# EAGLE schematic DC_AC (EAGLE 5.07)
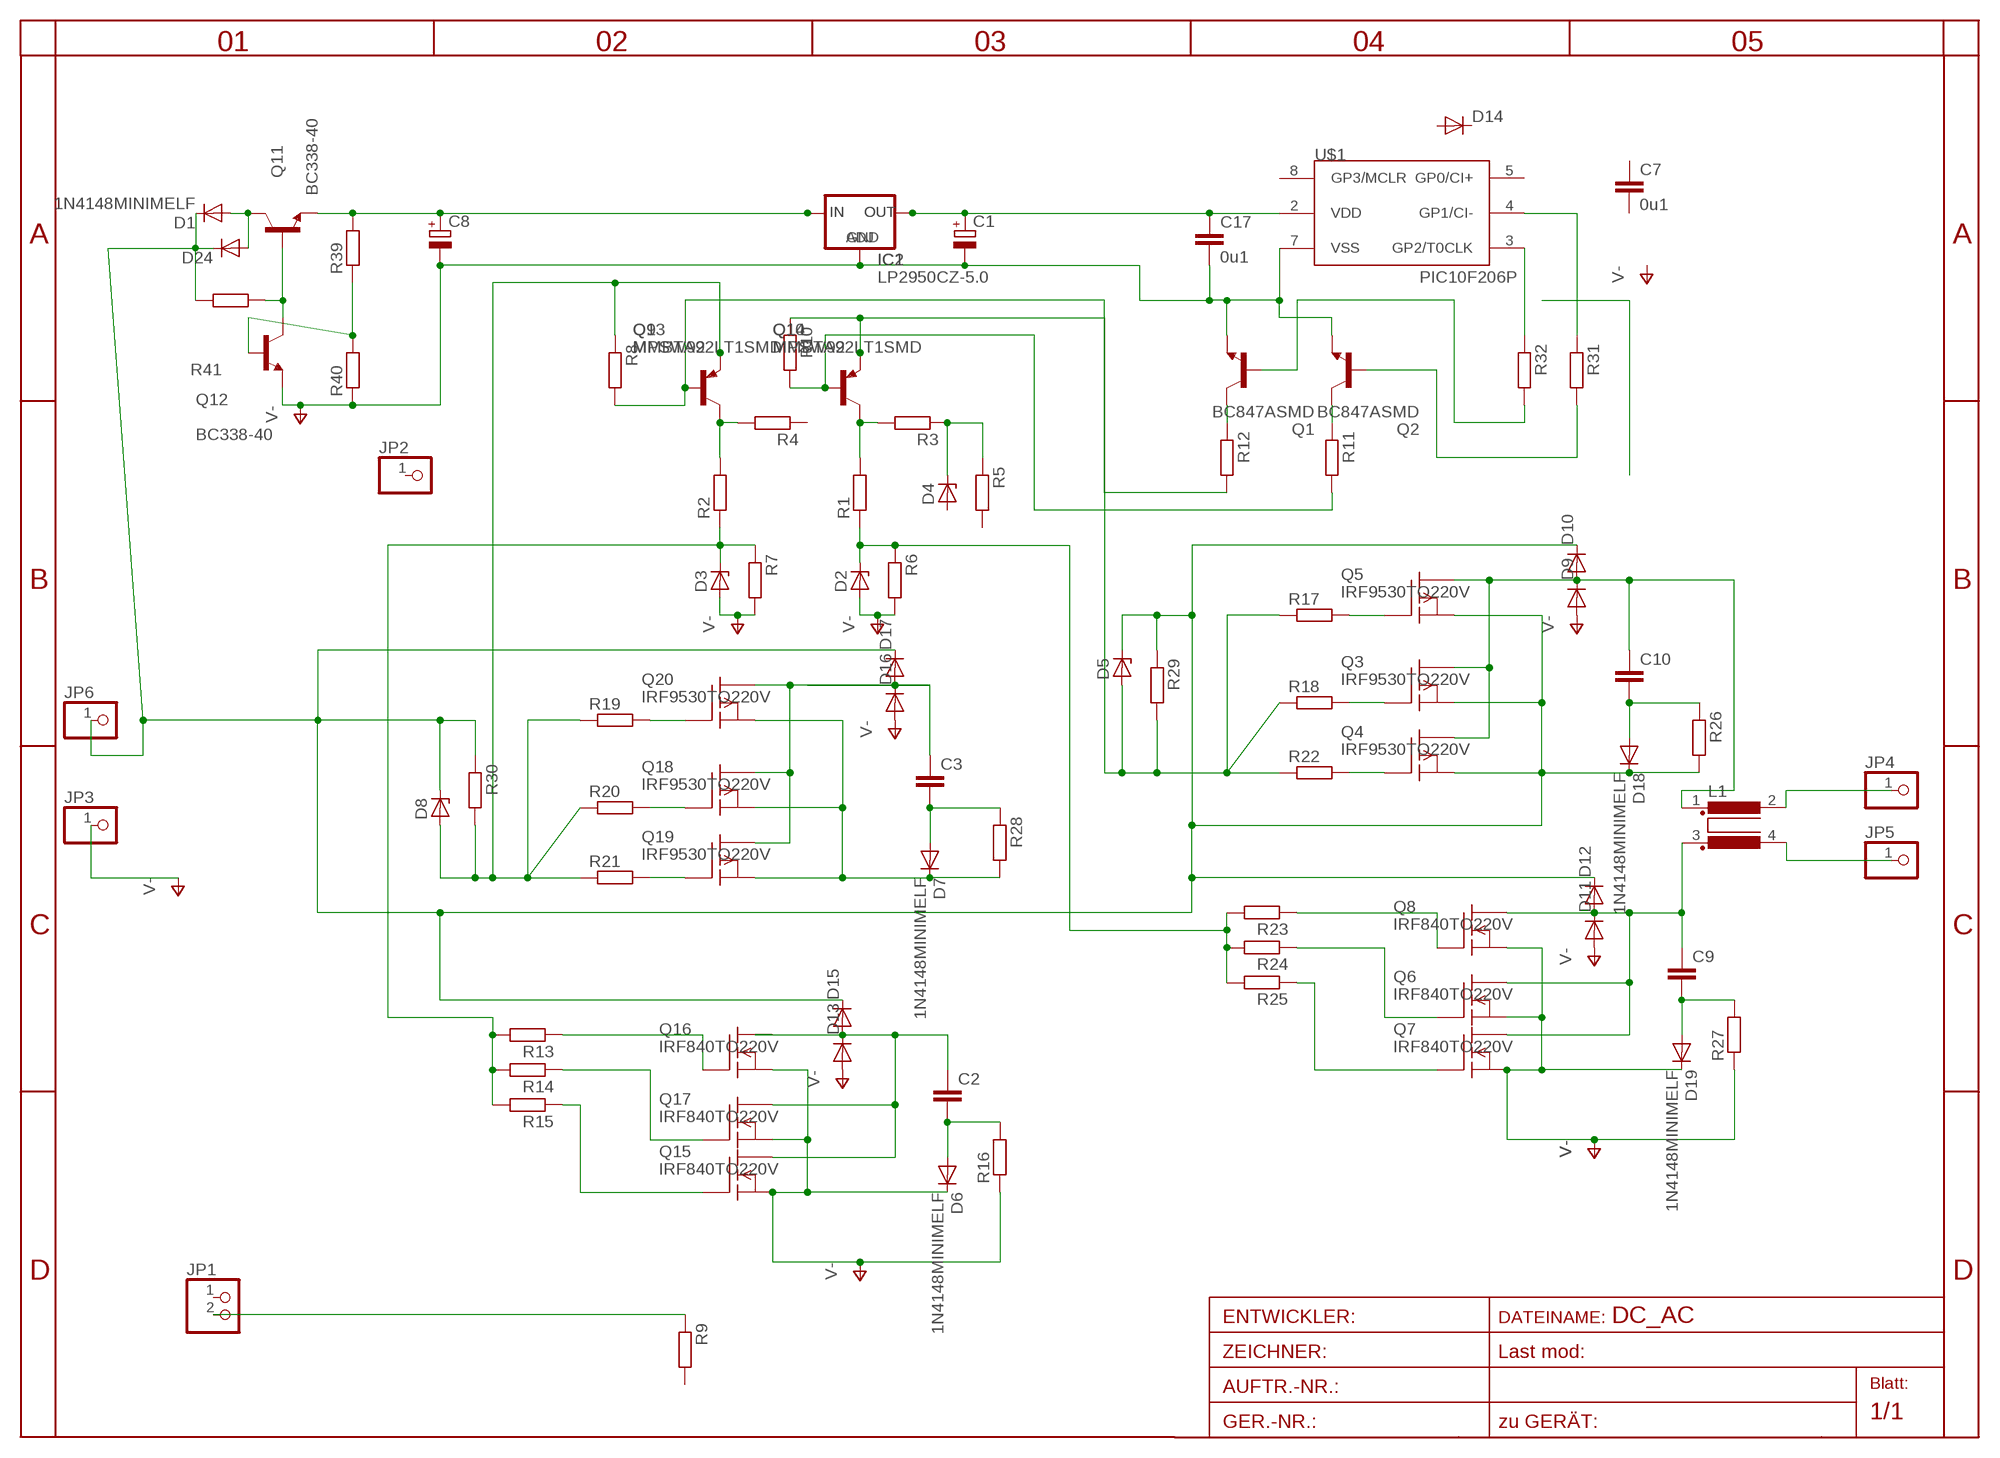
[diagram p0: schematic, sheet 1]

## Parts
C1  CPOL-EU5-13  [2,5-5-FLAT]
C2  C-EUC1812  [C1812]
C3  C-EUC1812K  [C1812K]
C7  0u1  C-EU050-025X075  [C050-025X075]
C8  CPOL-EU5-13  [2,5-5-FLAT]
C9  C-EUC1812  [C1812]
C10  C-EUC1812K  [C1812K]
C17  0u1  C-EU050-030X075  [C050-030X075]
D1  1N4148MINIMELF  [MINIMELF]
D2  ZENER-DIODESMB  [SMB]
D3  ZENER-DIODESMB  [SMB]
D4  ZENER-DIODESMB  [SMB]
D5  ZENER-DIODESMB  [SMB]
D6  1N4148MINIMELF  [MINIMELF]
D7  1N4148MINIMELF  [MINIMELF]
D8  ZENER-DIODESMB  [SMB]
D9  DIODE-SMC  [SMC]
D10  DIODE-SMC  [SMC]
D11  DIODE-SMC  [SMC]
D12  DIODE-SMC  [SMC]
D13  DIODE-SMC  [SMC]
D14  DIODE-D-5  [D-5]
D15  DIODE-SMC  [SMC]
D16  DIODE-SMC  [SMC]
D17  DIODE-SMC  [SMC]
D18  1N4148MINIMELF  [MINIMELF]
D19  1N4148MINIMELF  [MINIMELF]
D24  DIODE-D-7.5  [D-7.5]
IC1  LP2950CZ-5.0  [TO92]
IC2  LM317LZS  [TO92S]
JP1  PINHD-1X2  [1X02]
JP2  PINHD-1X11MM6  [1X1MM8]
JP3  PINHD-1X11MM6  [1X1MM8]
JP4  PINHD-1X14.5MM  [1X4MM5]
JP5  PINHD-1X14.5MM  [1X4MM5]
JP6  PINHD-1X11MM6  [1X1MM8]
L1  R1405VB2  [B2]
Q1  BC847ASMD  [SOT23]
Q2  BC847ASMD  [SOT23]
Q3  IRF9530TO220V  [TO220V]
Q4  IRF9530TO220V  [TO220V]
Q5  IRF9530TO220V  [TO220V]
Q6  IRF840TO220V  [TO220V]
Q7  IRF840TO220V  [TO220V]
Q8  IRF840TO220V  [TO220V]
Q9  MPSW92  [TO92-CBE]
Q10  MPSW92  [TO92-CBE]
Q11  BC338-40  [TO92-EBC]
Q12  BC338-40  [TO92-EBC]
Q13  MMBTA92LT1SMD  [SOT23-BEC]
Q14  MMBTA92LT1SMD  [SOT23-BEC]
Q15  IRF840TO220V  [TO220V]
Q16  IRF840TO220V  [TO220V]
Q17  IRF840TO220V  [TO220V]
Q18  IRF9530TO220V  [TO220V]
Q19  IRF9530TO220V  [TO220V]
Q20  IRF9530TO220V  [TO220V]
R1  R-EU_0207/10  [0207/10]
R2  R-EU_0207/10  [0207/10]
R3  R-EU_R1206  [R1206]
R4  R-EU_R1206  [R1206]
R5  R-EU_R1206  [R1206]
R6  R-EU_R1206  [R1206]
R7  R-EU_R1206  [R1206]
R8  R-EU_R1206  [R1206]
R9  R-EU_0207/10  [0207/10]
R10  R-EU_R1206  [R1206]
R11  R-EU_R1206  [R1206]
R12  R-EU_R1206  [R1206]
R13  R-EU_R1206  [R1206]
R14  R-EU_R1206  [R1206]
R15  R-EU_R1206  [R1206]
R16  R-EU_0207/30  [0207/30]
R17  R-EU_R1206  [R1206]
R18  R-EU_R1206  [R1206]
R19  R-EU_R1206  [R1206]
R20  R-EU_R1206  [R1206]
R21  R-EU_R1206  [R1206]
R22  R-EU_R1206  [R1206]
R23  R-EU_R1206  [R1206]
R24  R-EU_R1206  [R1206]
R25  R-EU_R1206  [R1206]
R26  R-EU_0207/25  [0207/25]
R27  R-EU_0207/30  [0207/30]
R28  R-EU_0207/25  [0207/25]
R29  R-EU_R1206  [R1206]
R30  R-EU_R1206  [R1206]
R31  R-EU_R1206  [R1206]
R32  R-EU_R1206  [R1206]
R39  R-EU_0207/10  [0207/10]
R40  R-EU_0204/2V  [0204V]
R41  R-EU_0207/10  [0207/10]
U$1  PIC10F206P  [DIL8]

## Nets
N$1: JP1.2 R9.1
N$2: C9.1 D11.C D12.A L1.3 Q6.2(D) Q7.2(D) Q8.2(D)
N$3: D13.C D15.A
N$4: Q3.1(G) R18.2
N$5: C1.+ C17.1 IC1.1(OUT) IC2.2(OUT) U$1.2(VDD)
N$6: C10.1 D9.C D10.A L1.1 Q3.2(D) Q4.2(D) Q5.2(D)
N$7: D16.C D17.A
N$10: D2.C R1.1 R6.1 R23.2 R24.2 R25.2
N$11: Q5.1(G) R17.2
N$12: D5.A Q10.E Q14.E R10.1 R17.1 R18.1 R22.1 R29.2
N$13: Q15.1(G) R15.1
N$14: C8.+ IC1.3(IN) IC2.3(IN) Q11.E R39.2
N$15: Q17.1(G) R14.1
N$16: Q9.B Q13.B R8.2 R12.2
N$17: JP5.1 L1.4
N$18: Q9.C Q13.C R2.2 R4.2
N$19: Q10.B Q14.B R10.2 R11.2
N$20: JP4.1 L1.2
N$21: Q10.C Q14.C R1.2 R3.2
N$22: Q16.1(G) R13.1
N$23: Q4.1(G) R22.2
N$24: C10.2 D18.A R26.1
N$25: Q7.1(G) R25.1
N$26: Q6.1(G) R24.1
N$27: Q8.1(G) R23.1
N$28: C9.2 D19.A R27.2
N$29: C2.2 D6.A R16.2
N$30: C2.1 Q15.2(D) Q16.2(D) Q17.2(D)
N$31: D3.C R2.1 R7.1 R13.2 R14.2 R15.2
N$32: Q18.1(G) R20.2
N$33: Q19.1(G) R21.2
N$34: Q20.1(G) R19.2
N$35: C3.2 D7.A R28.1
N$36: D1.A D24.A Q11.C
N$37: C3.1 Q18.2(D) Q19.2(D) Q20.2(D)
N$38: Q11.B Q12.C R41.1
N$39: R31.1 U$1.4(GP1/CI-)
N$40: D7.C Q18.3(S) Q19.3(S) Q20.3(S) R28.2
N$41: Q12.B R39.1 R40.2
N$42: Q2.1(B) R31.2
N$43: R32.1 U$1.3(GP2/T0CLK)
N$45: Q1.1(B) R32.2
N$48: Q1.3(C) R12.1
N$50: Q2.3(C) R11.1
N$52: D4.C R3.1 R5.1
V-: C1.- C8.- C17.2 D2.A D3.A D6.C D9.A D11.A D13.A D16.A D19.C IC1.2(GND) IC2.1(ADJ) JP3.1 Q1.2(E) Q2.2(E) Q6.3(S) Q7.3(S) Q8.3(S) Q12.E Q15.3(S) Q16.3(S) Q17.3(S) R6.2 R7.2 R16.1 R27.1 R40.1 U$1.7(VSS)
VIN: D1.C D5.C D8.C D10.C D12.C D15.C D17.C D18.C D24.C JP6.1 Q3.3(S) Q4.3(S) Q5.3(S) R26.2 R29.1 R30.1 R41.2
VIN2: D8.A Q9.E Q13.E R8.1 R19.1 R20.1 R21.1 R30.2
Unconnected: C7.1 C7.2 D4.A D14.A D14.C JP1.1 JP2.1 R4.1 R5.2 R9.2 U$1.5(GP0/CI+) U$1.8(GP3/MCLR)

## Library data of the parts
C1 C8 = rcl-2:CPOL-EU: POLARIZED CAPACITOR, European symbol
C2 C3 C7 C9 C10 C17 = rcl-2:C-EU: CAPACITOR, European symbol
D1 D6 D7 D18 D19 = diode-1:1N4148: DIODE
D2-D5 D8 = diode:ZENER-DIODE: Z-Diode
D9-D13 D15-D17 = diode:DIODE-: DIODE
D14 D24 = diode-1:DIODE-: DIODE
IC1 = v-reg:LP2950?*: Source: http://cache.national.com/ds/LP/LP2950.pdf
IC2 = v-reg-3:LM317L: Adjustable Voltage Regulator, 1.2V to 37V, 100mA
JP1 = pinhead:PINHD-1X2: PIN HEADER
JP2-JP6 = pinhead:PINHD-1X1: PIN HEADER
L1 = inductor-nkl:R1405V: Übertrager (verlustarm) bis typ. 400kHz Power transformer (low loss) up to typ. 400kHz
Q1 Q2 = transistor-npn:BC847*: NPN Transistor
Q3-Q5 Q18-Q20 = transistor-fet:IRF9530: P-Channel Enhancement MOSFET (HEXFET); -100V; -12A; 0,3Ohm
Q6-Q8 Q15-Q17 = transistor-fet:IRF840: N-Channel Enhancement MOSFET (HEXFET); 500V; 8A; 0,85Ohm
Q9 Q10 = transistor-pnp:MPSW92*: PNP Transistror
Q11 Q12 = transistor-npn:BC338*: NPN Transistor
Q13 Q14 = transistor-pnp:MMBTA92*: PNP Transistror
R1-R32 R39-R41 = rcl-2:R-EU_: RESISTOR, European symbol
U$1 = microchip-5:PIC10F2*: uPC nW 0,25/0,5k Program Flash memory Comparator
